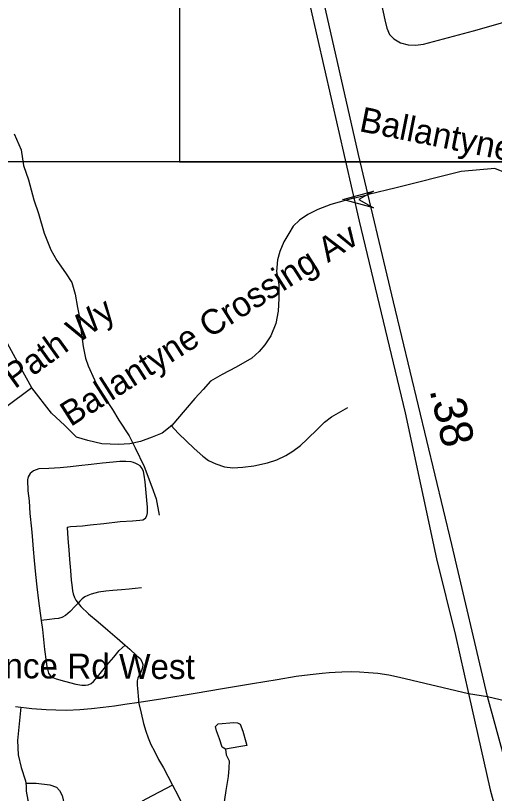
# Model space of a CAD drawing. Extents: x 1383679 to 1536984, y 460658 to 651027.
# Drawn here: x 1445570 to 1447399, y 474906 to 477874 of the extents above; entities that cross this region are included whole.
import ezdxf

# ---------------------------------------------------------------- set-up
doc = ezdxf.new("R2010")
doc.units = 0
for name, color, linetype in [('Exist Hydrographic Misc Water Feature', 7, 'Continuous'), ('Exist Road Non-System Type 51', 7, 'Continuous'), ('Exist Road Non-System Type 51 Label', 7, 'Continuous'), ('Exist Road Primary Interstate Structure Vehicle Undrpass Attributed CELL', 7, 'Continuous'), ('Exist Road Primary US Divided Attributed', 7, 'Continuous'), ('Exist Road Secondary Mileage Hundredths English Label', 7, 'Continuous'), ('Map Preparation Inset Cut Line', 7, 'Continuous')]:
    doc.layers.add(name, color=color, linetype=linetype)

msp = doc.modelspace()

# ---------------------------------------------------------------- linework, layer by layer
at = {"layer": 'Exist Hydrographic Misc Water Feature'}
for points in [[(1445564.6, 477422.3), (1445591.6, 477361.9), (1445600.5, 477301.8), (1445619.4, 477247.2), (1445640.1, 477170.5), (1445657.2, 477118.5), (1445679.8, 477044.1), (1445704.5, 476979.6), (1445727.8, 476938.9), (1445761, 476892.3), (1445784.4, 476855.7), (1445797.5, 476811.2), (1445806.7, 476759.3), (1445815.9, 476714.8), (1445817.3, 476685.2), (1445822.6, 476649), (1445827.9, 476611.2), (1445837.2, 476566.7), (1445846.6, 476536.9), (1445871.7, 476483.9), (1445889, 476445.8), (1445908.5, 476417.5), (1445939.6, 476371), (1445964.9, 476330.2), (1446003.8, 476269.6), (1446027, 476224.7), (1446061.6, 476152.7), (1446090.2, 476075.8), (1446107.4, 476029.5), (1446118.2, 475967.7)], [(1446372.1, 475074.7), (1446358.3, 475082.4), (1446348.8, 475114.6), (1446337.4, 475145.1), (1446333.7, 475160.8), (1446343.9, 475171.3), (1446404, 475175.8), (1446418, 475175.5), (1446427.9, 475169.6), (1446437.4, 475143.2), (1446448.7, 475102.7), (1446452.4, 475088.7), (1446422.3, 475083.5), (1446372.1, 475074.7)], [(1446372.1, 475074.7), (1446373.7, 475052.5), (1446385.3, 475030.1), (1446384.8, 475002.2), (1446382.2, 474970.3), (1446373.2, 474916.3), (1446364.1, 474856.6), (1446355.2, 474804.3), (1446352.6, 474772.3), (1446344.2, 474754.4), (1446329.9, 474740.7), (1446303.6, 474717.5)]]:
    msp.add_lwpolyline(points, dxfattribs=at)
at = {"layer": 'Exist Road Non-System Type 51'}
for points in [[(1447079.9, 478238.9), (1447093.6, 478180.9), (1447106.4, 478122.8), (1447017, 478104.2), (1446933.1, 478086.5), (1446952.5, 477987.8), (1446979.8, 477857.6), (1446987.1, 477825.5), (1446997.4, 477801.9), (1447014.4, 477785.6), (1447040.4, 477769.8), (1447069.4, 477761.9), (1447096.6, 477761.3), (1447127.5, 477764.3), (1447318.2, 477815.8), (1447447.9, 477852.8), (1447493.9, 477866.7), (1447515.1, 477877.6), (1447531.4, 477893.3), (1447536.9, 477909.7), (1447541.4, 477933.1), (1447538.1, 477963.1), (1447533.9, 477992.7), (1447519.9, 478054.4)], [(1447705.5, 477121.8), (1447519.9, 477241.8), (1447399.9, 477290.4), (1447271.4, 477279), (1447023.7, 477216.4), (1446917.5, 477190.9)], [(1446860.4, 477176.6), (1446774, 477152.6), (1446723.7, 477133.7), (1446685.9, 477114.8), (1446654.5, 477092.8), (1446629.3, 477070.8), (1446613.6, 477042.4), (1446594.7, 477011), (1446579, 476973.2), (1446569.5, 476941.7), (1446566.4, 476897.6), (1446575.8, 476847.3), (1446575.8, 476793.7), (1446572.7, 476746.5), (1446563.2, 476699.3), (1446544.4, 476652.1), (1446522.3, 476617.5), (1446500.3, 476592.3), (1446472, 476567.1), (1446412.2, 476532.5), (1446358.8, 476504.1), (1446314.7, 476479), (1446286.4, 476447.5), (1446255, 476412.9), (1446217.2, 476368.8), (1446166.9, 476309), (1446129.1, 476280.6), (1446091.4, 476264.9), (1446047.4, 476249.2), (1446006.5, 476239.7), (1445962.4, 476236.6), (1445899.5, 476239.7), (1445846, 476252.3), (1445802, 476264.9), (1445758, 476309), (1445707.6, 476356.2), (1445632.1, 476453.8)], [(1446860.4, 477176.6), (1446917.5, 477190.9)], [(1445632.1, 476453.8), (1445585, 476538.8), (1445547.2, 476608), (1445509.5, 476674.1), (1445487.4, 476737.1), (1445462.3, 476800), (1445427.7, 476881.9), (1445405.7, 476922.8), (1445380.5, 476963.7), (1445345.9, 477004.7), (1445311.3, 477039.3), (1445261, 477070.8), (1445232.6, 477099.1)], [(1445632.1, 476453.8), (1445531.5, 476378.2)], [(1446163, 476311.3), (1446191.9, 476279.2), (1446252.4, 476222.5), (1446284.6, 476192.2), (1446306.4, 476176.1), (1446334.8, 476162.8), (1446367.9, 476152.4), (1446400.1, 476148.7), (1446437.9, 476150.6), (1446479.5, 476156.2), (1446531.6, 476167.6), (1446567.5, 476178.9), (1446601.6, 476195), (1446629.1, 476212.1), (1446657.4, 476233.8), (1446683.9, 476257.5), (1446724.6, 476297.2), (1446750.1, 476321.8), (1446775.8, 476342.7), (1446839.1, 476377.7)], [(1445766.9, 475922.2), (1445779.8, 475923.8), (1445802.9, 475925.6), (1445825.6, 475927.4), (1445855.1, 475930.5), (1445907.4, 475935.8), (1445969.4, 475943), (1446016.1, 475946.2), (1446043.9, 475948.3), (1446056.4, 475950.2), (1446065.6, 475955.9), (1446071.1, 475964.4), (1446073.6, 475976.3), (1446073.8, 475985.3), (1446073.2, 475998.1), (1446070.8, 476025.2), (1446066.9, 476067.2), (1446065.4, 476094.2), (1446061.4, 476119.8), (1446057.9, 476134.2), (1446053, 476145.5), (1446046, 476155.3), (1446037.1, 476160.8), (1446028.9, 476164.8), (1446020.5, 476168.4), (1446011.8, 476170.9), (1445990.9, 476172.8), (1445967.5, 476171.8), (1445942.5, 476169.8), (1445902.2, 476165.3), (1445858.6, 476160.4), (1445812, 476155.5), (1445780.1, 476152.1), (1445740.2, 476148.7)], [(1445740.2, 476148.7), (1445697.1, 476146), (1445658.5, 476143.8), (1445638.1, 476137.2), (1445626.1, 476127.1), (1445617.6, 476114.1), (1445615.8, 476102.4), (1445616.9, 476059.7), (1445621.8, 476022), (1445624.9, 475973.3), (1445630.6, 475915.8), (1445632.9, 475887.2), (1445637.4, 475838.2), (1445641.4, 475794.9), (1445645.9, 475740.5), (1445651.6, 475693.6), (1445657.9, 475640.5), (1445667.6, 475565.4)], [(1445766.9, 475922.2), (1445768.8, 475897.8), (1445771.2, 475863.2), (1445773.5, 475835), (1445775.6, 475798.4), (1445779.4, 475756.8), (1445781.9, 475719.6), (1445784.4, 475701.8), (1445786.9, 475678.9), (1445789.5, 475667.3), (1445794.9, 475653.9), (1445800.6, 475643.2), (1445808.6, 475631.9)], [(1446051, 475690.5), (1446026.9, 475688.2), (1446004.1, 475685.6), (1445974.2, 475682.5), (1445941.6, 475679.8), (1445914.9, 475677.1), (1445886.4, 475673.2), (1445858.2, 475666.2), (1445845.9, 475661.4), (1445834.6, 475655.5), (1445824.5, 475647.7), (1445815, 475638.8), (1445808.6, 475631.9)], [(1445808.6, 475631.9), (1445797.2, 475619.7), (1445778.4, 475599.7), (1445760.1, 475584.3), (1445746.6, 475577.2), (1445733.8, 475573.6), (1445718.1, 475571.3), (1445699.4, 475569.6), (1445667.6, 475565.4)], [(1445808.6, 475631.9), (1445819.1, 475618.6), (1445848.9, 475590.7), (1445884.8, 475560.6), (1445922.1, 475529.1), (1445957.9, 475498.4), (1445988.1, 475471.8)], [(1445667.6, 475565.4), (1445672.2, 475531.2), (1445680.2, 475454.9), (1445686.6, 475408.8), (1445689.6, 475390.1), (1445693.1, 475374.4), (1445696.2, 475364.2), (1445702.2, 475355.8), (1445712.9, 475348.2), (1445725.2, 475342.9), (1445756.2, 475334.2), (1445800, 475322.9), (1445822.5, 475318.4), (1445837.5, 475318.8), (1445846.6, 475320.6), (1445858.1, 475324.6), (1445867.1, 475332.8), (1445882.9, 475350.9), (1445898.5, 475370.2), (1445919, 475395), (1445945, 475425.8), (1445966.1, 475450.5), (1445988.1, 475471.8)], [(1445988.1, 475471.8), (1446005.9, 475456.2), (1446031.5, 475432.1), (1446045.6, 475420.2), (1446052.4, 475409.4), (1446055.4, 475398.2), (1446055, 475385.8), (1446051.4, 475374.7), (1446036.8, 475345.5), (1446034.4, 475335.2), (1446034.8, 475319.1), (1446035.1, 475306.4), (1446038.8, 475263.2), (1446039.8, 475253.8)], [(1445569.3, 475237.3), (1445632.6, 475229.6), (1445686.3, 475225.6), (1445724.2, 475224.8), (1445766.2, 475223.8), (1445815.4, 475226.3), (1445860.1, 475229.9), (1445904.6, 475235.1), (1445947.2, 475240.3), (1445987.5, 475245.7), (1446041.3, 475254), (1446132, 475268), (1446256.2, 475287.8), (1446359.7, 475306), (1446475, 475324.8), (1446569.3, 475340.9), (1446641.4, 475352.7), (1446695.4, 475359.7), (1446741.1, 475365), (1446767.5, 475367.7), (1446790.4, 475369), (1446816, 475369.7), (1446853.3, 475370.7), (1446882.7, 475369.4), (1446917.8, 475367.4), (1446953.2, 475364.2), (1446994.8, 475357.9), (1447035.5, 475349.6), (1447299.6, 475287.3)], [(1447299.6, 475287.3), (1447372.3, 475275.1)], [(1447372.3, 475275.1), (1447512.1, 475242.4)], [(1446039.8, 475253.8), (1446049.4, 475212.2), (1446058.2, 475172.9), (1446067, 475142.7), (1446075.9, 475118.3), (1446086.5, 475092.9), (1446100.1, 475066.7), (1446115.8, 475035.4), (1446134.2, 475003.2), (1446150.9, 474971.1), (1446169.4, 474937)], [(1445589.6, 475235.2), (1445576.8, 475108.2), (1445580.1, 475053.2), (1445591.6, 475005), (1445607.6, 474953.4), (1445608.6, 474945.4)], [(1446372.1, 475074.7), (1446373.7, 475052.5), (1446385.3, 475030.1), (1446384.8, 475002.2), (1446382.2, 474970.3), (1446373.2, 474916.3), (1446364.1, 474856.6), (1446355.2, 474804.3), (1446352.6, 474772.3), (1446344.2, 474754.4), (1446329.9, 474740.7), (1446303.6, 474717.5)], [(1445608.6, 474945.4), (1445610, 474932.8), (1445610, 474914.4), (1445616.9, 474880), (1445632.9, 474831.8), (1445629.5, 474813.5), (1445620.4, 474796.3), (1445604.2, 474783.8), (1445516, 474749.3), (1445501.1, 474740.2), (1445488.5, 474724.1), (1445485, 474705.8), (1445486.1, 474684), (1445496.5, 474665.7), (1445501.1, 474656.4)], [(1445608.6, 474945.4), (1445649, 474945.3), (1445700.6, 474938.5), (1445725.8, 474929.3), (1445737.2, 474916.8), (1445747.6, 474898.3), (1445763.6, 474831.8), (1445769.4, 474792.9)], [(1446169.4, 474937), (1446068, 474883.3), (1445911, 474796.6), (1445888.6, 474792.9), (1445861.1, 474788.3), (1445816.4, 474790.6), (1445769.4, 474792.9)], [(1446169.4, 474937), (1446191.4, 474896.8), (1446212.6, 474851.2), (1446219.8, 474819.8), (1446223.9, 474789.2), (1446224, 474757.6), (1446219.8, 474706.1)]]:
    msp.add_lwpolyline(points, dxfattribs=at)
at = {"layer": 'Exist Road Primary Interstate Structure Vehicle Undrpass Attributed CELL'}
msp.add_lwpolyline([(1446937, 477140.2), (1446819.2, 477171.8), (1446937, 477203.3), (1446880.2, 477171.8)], close=True, dxfattribs=at)
at = {"layer": 'Exist Road Primary US Divided Attributed'}
for points in [[(1447372.3, 475275.1), (1447235.2, 475855.2), (1447012.5, 476781.4), (1446879.9, 477343.6), (1446667.5, 478274.3), (1446525.1, 478854.3), (1446451.7, 479175.7), (1446401.9, 479385.7), (1446351.3, 479733.5), (1446344.1, 479929.8), (1446339.3, 480024), (1446345.3, 480221.8), (1446360.1, 480316.9), (1446384.9, 480437.7), (1446410.6, 480540.9), (1446450, 480723.4), (1446487.7, 480884.4), (1446596.7, 481144.2), (1446701.2, 481343.7)], [(1446694.3, 477908.5), (1446881.8, 477089.9), (1447058, 476358.3), (1447177.8, 475801.3), (1447250.2, 475507.8), (1447299.6, 475287.3)], [(1447299.6, 475287.3), (1447382, 474918.8), (1447465, 474617.7), (1447541.7, 474311.7), (1447580.1, 474105), (1447601.4, 473960.3), (1447601.4, 473745.3), (1447588.6, 473646), (1447554.5, 473534.4), (1447516.2, 473426.9), (1447439.4, 473273.9), (1447274, 473035.3), (1446944.2, 472703.3)], [(1447000.3, 472660.9), (1447258.3, 472914.2), (1447394.7, 473067.2), (1447462.9, 473158.1), (1447518.3, 473245), (1447582.2, 473369), (1447629.1, 473488.9), (1447658.9, 473604.7), (1447671.7, 473712.2), (1447688.8, 473840.3), (1447684.5, 473947.8), (1447658.9, 474109.1), (1447624.8, 474286.9), (1447516.2, 474750), (1447372.3, 475275.1)]]:
    msp.add_lwpolyline(points, dxfattribs=at)
at = {"layer": 'Map Preparation Inset Cut Line'}
for points in [[(1446195.4, 477316), (1383679.3, 477316), (1383679.3, 520758.2), (1458567.8, 520758.2), (1458567.8, 493672.2), (1446195.4, 493672.2), (1446195.4, 477316)], [(1446195.4, 477316), (1480703, 477316), (1498974.3, 494868.2), (1521133.6, 516155.5), (1521133.6, 520758.2), (1458567.8, 520758.2), (1458567.8, 493672.2), (1446195.4, 493672.2), (1446195.4, 477316)], [(1437474.3, 477316), (1437474.3, 461213.3), (1475802.8, 461213.3), (1475802.8, 477316), (1437474.3, 477316)]]:
    msp.add_lwpolyline(points, dxfattribs=at)

# ---------------------------------------------------------------- texts
at = {"layer": 'Exist Road Non-System Type 51 Label'}
for s, rotation, p in [('Ballantyne Crossing Av', 348.6624, (1446878.7, 477433.2)), ('Ballantyne Crossing Av', 32.5126, (1445780, 476303)), ('Trading Path Wy', 35.6808, (1445188.6, 476175.3)), ('Providence Rd West', 359.721, (1445096.3, 475347.4))]:
    msp.add_text(s, height=95, rotation=rotation, dxfattribs=at).set_placement(p)
at = {"layer": 'Exist Road Secondary Mileage Hundredths English Label'}
msp.add_text('.38', height=125, rotation=283.1656, dxfattribs=at).set_placement((1447150.1, 476444.9))

doc.saveas('drawing.dxf')
